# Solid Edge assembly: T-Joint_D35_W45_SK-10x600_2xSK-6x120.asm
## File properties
Author: fknapp
Template: iso metric assembly.asm
Last saved by: fknapp
Revision: 16
Application: Solid Edge
Username: fknapp
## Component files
T-Joint_D35_W45.par
SK Schraube 6x120_ohne_Gewinde.par
SK Schraube 10x600_ohne_Gewinde_22042020.par
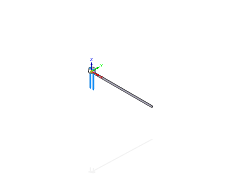
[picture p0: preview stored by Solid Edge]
